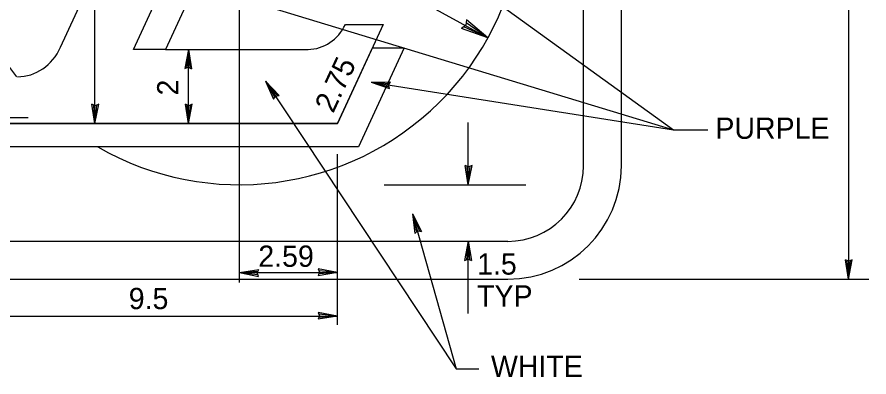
# Model space of a CAD drawing. Extents: x 10268197 to 10269179, y 2141503 to 2142677.
# Drawn here: x 10268787.54 to 10268815.69, y 2142157.43 to 2142169.35 of the extents above; entities that cross this region are included whole.
import ezdxf

# ---------------------------------------------------------------- set-up
doc = ezdxf.new("R2010")
doc.units = 0
for name, color, linetype in [('1', 7, 'Continuous'), ('Default', 7, 'Continuous'), ('TextMisc', 7, 'Continuous'), ('TextShtNo', 7, 'Continuous')]:
    doc.layers.add(name, color=color, linetype=linetype)

msp = doc.modelspace()

# ---------------------------------------------------------------- linework, layer by layer
at = {"layer": '1'}
for p, q in [((10268799.317, 2142172.781), (10268809.237, 2142165.62)), ((10268795.09, 2142169.924), (10268809.237, 2142165.62)), ((10268799.239, 2142167.189), (10268809.237, 2142165.62)), ((10268809.237, 2142165.62), (10268810.37, 2142165.62))]:
    msp.add_line(p, q, dxfattribs=at)
at = {"layer": 'Default'}
for p, q in [((10268815.015, 2142185.674), (10268815.015, 2142160.674)), ((10268806.259, 2142164.424), (10268806.259, 2142181.923)), ((10268790.112, 2142165.824), (10268790.112, 2142180.557)), ((10268788.978, 2142168.346), (10268793.447, 2142178.097)), ((10268794.885, 2142160.56), (10268794.885, 2142173.174)), ((10268794.885, 2142173.174), (10268803.102, 2142168.661)), ((10268791.389, 2142168.279), (10268793.233, 2142172.269)), ((10268793.927, 2142171.494), (10268792.441, 2142168.279)), ((10268799.639, 2142169.106), (10268798.123, 2142165.824)), ((10268798.389, 2142169.106), (10268799.639, 2142169.106)), ((10268802.39, 2142169.253), (10268802.371, 2142169.079)), ((10268803.102, 2142168.661), (10268802.381, 2142169.161)), ((10268803.102, 2142168.661), (10268802.39, 2142169.253)), ((10268802.371, 2142169.079), (10268802.231, 2142168.974)), ((10268803.102, 2142168.661), (10268802.231, 2142168.974)), ((10268803.102, 2142168.661), (10268802.306, 2142169.029)), ((10268792.441, 2142168.279), (10268791.389, 2142168.279)), ((10268792.441, 2142168.279), (10268797.154, 2142168.279)), ((10268793.206, 2142168.279), (10268793.083, 2142167.643)), ((10268793.206, 2142168.279), (10268793.142, 2142167.668)), ((10268793.206, 2142165.824), (10268793.206, 2142168.279)), ((10268793.206, 2142168.279), (10268793.307, 2142167.639)), ((10268793.206, 2142168.279), (10268793.249, 2142167.666)), ((10268800.333, 2142168.33), (10268798.817, 2142165.048)), ((10268799.281, 2142168.33), (10268800.333, 2142168.33)), ((10268793.083, 2142167.643), (10268793.196, 2142167.69)), ((10268793.196, 2142167.69), (10268793.307, 2142167.639)), ((10268795.753, 2142167.222), (10268796.203, 2142166.756)), ((10268795.753, 2142167.222), (10268796.018, 2142166.631)), ((10268795.753, 2142167.222), (10268796.053, 2142166.684)), ((10268795.753, 2142167.222), (10268796.14, 2142166.745)), ((10268795.754, 2142167.222), (10268802.045, 2142157.706)), ((10268799.239, 2142167.189), (10268799.884, 2142167.201)), ((10268799.239, 2142167.189), (10268799.849, 2142166.979)), ((10268799.239, 2142167.189), (10268799.833, 2142167.041)), ((10268799.239, 2142167.189), (10268799.85, 2142167.147)), ((10268799.818, 2142167.098), (10268799.884, 2142167.201)), ((10268799.849, 2142166.979), (10268799.818, 2142167.098)), ((10268796.018, 2142166.631), (10268796.083, 2142166.734)), ((10268796.083, 2142166.734), (10268796.203, 2142166.756)), ((10268790.112, 2142165.824), (10268790.012, 2142166.463)), ((10268790.122, 2142166.413), (10268790.012, 2142166.463)), ((10268790.112, 2142165.824), (10268790.07, 2142166.436)), ((10268790.112, 2142165.824), (10268790.236, 2142166.46)), ((10268790.112, 2142165.824), (10268790.176, 2142166.435)), ((10268790.236, 2142166.46), (10268790.122, 2142166.413)), ((10268793.206, 2142165.824), (10268793.105, 2142166.463)), ((10268793.215, 2142166.413), (10268793.105, 2142166.463)), ((10268793.206, 2142165.824), (10268793.163, 2142166.436)), ((10268793.206, 2142165.824), (10268793.329, 2142166.46)), ((10268793.206, 2142165.824), (10268793.269, 2142166.435)), ((10268793.329, 2142166.46), (10268793.215, 2142166.413)), ((10268786.001, 2142166.026), (10268787.909, 2142166.026)), ((10268798.123, 2142165.824), (10268786.874, 2142165.824)), ((10268802.452, 2142163.799), (10268802.452, 2142165.861)), ((10268798.817, 2142165.048), (10268786.517, 2142165.048)), ((10268798.123, 2142159.16), (10268798.123, 2142164.806)), ((10268802.452, 2142163.799), (10268802.352, 2142164.438)), ((10268802.462, 2142164.387), (10268802.352, 2142164.438)), ((10268802.452, 2142163.799), (10268802.41, 2142164.411)), ((10268802.452, 2142163.799), (10268802.576, 2142164.434)), ((10268802.452, 2142163.799), (10268802.516, 2142164.41)), ((10268802.576, 2142164.434), (10268802.462, 2142164.387)), ((10268799.67, 2142163.799), (10268804.357, 2142163.799)), ((10268800.608, 2142162.83), (10268802.045, 2142157.706)), ((10268800.608, 2142162.83), (10268800.9, 2142162.252)), ((10268800.608, 2142162.83), (10268800.686, 2142162.187)), ((10268800.608, 2142162.83), (10268800.735, 2142162.228)), ((10268800.608, 2142162.83), (10268800.837, 2142162.26)), ((10268800.686, 2142162.187), (10268800.779, 2142162.266)), ((10268800.779, 2142162.266), (10268800.9, 2142162.252)), ((10268778.76, 2142161.924), (10268803.759, 2142161.924)), ((10268802.452, 2142161.924), (10268802.33, 2142161.288)), ((10268802.452, 2142161.924), (10268802.389, 2142161.312)), ((10268802.452, 2142159.531), (10268802.452, 2142161.924)), ((10268802.452, 2142161.924), (10268802.554, 2142161.284)), ((10268802.452, 2142161.924), (10268802.496, 2142161.311)), ((10268802.33, 2142161.288), (10268802.443, 2142161.335)), ((10268802.443, 2142161.335), (10268802.554, 2142161.284)), ((10268815.015, 2142160.674), (10268814.914, 2142161.313)), ((10268815.025, 2142161.262), (10268814.914, 2142161.313)), ((10268815.015, 2142160.674), (10268814.973, 2142161.286)), ((10268815.015, 2142160.674), (10268815.138, 2142161.309)), ((10268815.015, 2142160.674), (10268815.079, 2142161.285)), ((10268815.138, 2142161.309), (10268815.025, 2142161.262)), ((10268794.885, 2142160.887), (10268795.524, 2142160.989)), ((10268795.473, 2142160.877), (10268795.524, 2142160.989)), ((10268798.123, 2142160.887), (10268797.488, 2142161.011)), ((10268797.488, 2142161.011), (10268797.534, 2142160.898)), ((10268798.123, 2142160.887), (10268797.512, 2142160.951)), ((10268794.885, 2142160.887), (10268795.497, 2142160.931)), ((10268794.885, 2142160.887), (10268798.123, 2142160.887)), ((10268794.885, 2142160.887), (10268795.52, 2142160.764)), ((10268794.885, 2142160.887), (10268795.496, 2142160.824)), ((10268795.52, 2142160.764), (10268795.473, 2142160.877)), ((10268797.534, 2142160.898), (10268797.484, 2142160.786)), ((10268798.123, 2142160.887), (10268797.484, 2142160.786)), ((10268798.123, 2142160.887), (10268797.51, 2142160.844)), ((10268798.123, 2142159.45), (10268797.488, 2142159.572)), ((10268797.488, 2142159.572), (10268797.534, 2142159.459)), ((10268786.248, 2142159.45), (10268798.123, 2142159.45)), ((10268797.534, 2142159.459), (10268797.484, 2142159.348)), ((10268798.123, 2142159.45), (10268797.484, 2142159.348)), ((10268798.123, 2142159.45), (10268797.51, 2142159.406)), ((10268798.123, 2142159.45), (10268797.512, 2142159.513)), ((10268802.045, 2142157.706), (10268802.802, 2142157.706))]:
    msp.add_line(p, q, dxfattribs=at)
for centre, major_axis, ratio, start_param, end_param in [((10268794.884, 2142173.173), (0, 9.375), 0.999997, 5.619293, 8.52162), ((10268794.884, 2142173.173), (0, 9.375), 0.999997, 2.619545, 5.22594), ((10268797.154, 2142169.814), (0, 1.535), 0.906665, 3.141593, 4.233038), ((10268787.552, 2142169.156), (0, 1.784), 0.897227, 3.141593, 4.241135), ((10268803.759, 2142164.423), (0, -2.5), 0.999997, 0, 1.570796)]:
    msp.add_ellipse(centre, major_axis=major_axis, ratio=ratio, start_param=start_param, end_param=end_param, dxfattribs=at)
at = {"layer": 'TextMisc'}
for p, q in [((10268807.509, 2142164.424), (10268807.509, 2142181.923)), ((10268778.76, 2142160.674), (10268803.759, 2142160.674)), ((10268806.117, 2142160.674), (10268815.693, 2142160.674))]:
    msp.add_line(p, q, dxfattribs=at)
msp.add_ellipse((10268803.759, 2142164.423), major_axis=(0, -3.75), ratio=0.999998, start_param=0, end_param=1.570796, dxfattribs=at)
at = {"layer": 'TextShtNo'}
for p, q in [((10268791.389, 2142168.279), (10268793.233, 2142172.269)), ((10268793.927, 2142171.494), (10268792.441, 2142168.279)), ((10268792.441, 2142168.279), (10268791.389, 2142168.279)), ((10268798.123, 2142165.824), (10268799.281, 2142168.33)), ((10268800.333, 2142168.33), (10268798.817, 2142165.048)), ((10268799.281, 2142168.33), (10268800.333, 2142168.33)), ((10268786.874, 2142165.824), (10268798.123, 2142165.824)), ((10268798.817, 2142165.048), (10268786.517, 2142165.048))]:
    msp.add_line(p, q, dxfattribs=at)

# ---------------------------------------------------------------- texts
at = {"layer": '1'}
for s, height, rotation, p in [('2.75', 0.7047, 65.0602, (10268797.986, 2142166.139)), ('2', 0.705, 90, (10268792.872, 2142166.751))]:
    msp.add_text(s, height=height, rotation=rotation, dxfattribs=at).set_placement(p)
for s, p in [('PURPLE', (10268810.618, 2142165.317)), ('2.59', (10268795.511, 2142161.08)), ('1.5', (10268802.742, 2142160.822)), ('9.5', (10268791.229, 2142159.679)), ('TYP', (10268802.742, 2142159.765)), ('WHITE', (10268803.2, 2142157.434))]:
    msp.add_text(s, height=0.7047, dxfattribs=at).set_placement(p)

doc.saveas('drawing.dxf')
